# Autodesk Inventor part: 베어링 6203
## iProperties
IsCustomPart: 0
Company: 한국ATC센터
Created: 2014-10
Part Number: 베어링 6203
Material: Steel, Mild
Description: 깊은 그루브 볼 베어링
Document SubType Name: Modeling
Standard: KS B 2023
Designer: KYOUNG IL JANG
Standards Organization: KS
Language: ko-KR
Size Designation: 6203 - 17 x 40 x 12
Categories: <MemberInstance><Categories><Category DisplayName="샤프트 부품" InternalName="7f7aeb1f-a693-4053-b835-cee3144e0d98" Mnemonic="SHFT"><Category DisplayName="베어링" Inter
Density: 7.86 g/cm^3
Mass: 64.9809 g
Surface Area: 64.3582 cm^2
Volume: 8.26729 cm^3
Author: KYOUNG IL JANG
Revision Number: 1
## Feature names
1. IDS_ARRAYBALL[SIMPL:T] [Circular Pattern]
